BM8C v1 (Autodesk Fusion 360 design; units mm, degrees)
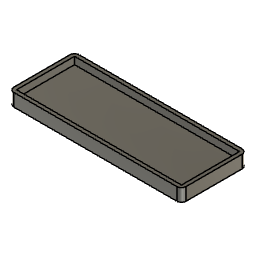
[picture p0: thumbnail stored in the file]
sketch "Sketch1" plane through (0, 0, 0) normal (0, 0, 1) x axis (1, 0, 0)
  line L1 (91, 0) -> (0, 0)
  line L2 (91, 32) -> (91, 0)
  line L3 (0, 32) -> (91, 32)
  line L4 (0, 0) -> (0, 32)
  line L5 (93, -2) -> (-2, -2)
  line L6 (93, 34) -> (93, -2)
  line L7 (-2, 34) -> (93, 34)
  line L8 (-2, -2) -> (-2, 34)
  point P1 (0, 0)
  point P2 (0, 0)
  point P3 (91, 0)
  point P5 (0, 32)
  horizontal L1
  vertical L2
  horizontal L3
  vertical L4
  coincident P1 P2
  dimension "d1" distance P2 P3 = 91
  dimension "d2" distance P2 P5 = 32
  dimension "d3" = 2
extrude "Extrude1" new body sketch "Sketch1" against normal blind 7
extrude "Extrude2" cut sketch "Sketch1" profile of L1 L2 L3 L4 against normal blind 4
fillet "Fillet1" radius 2.5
